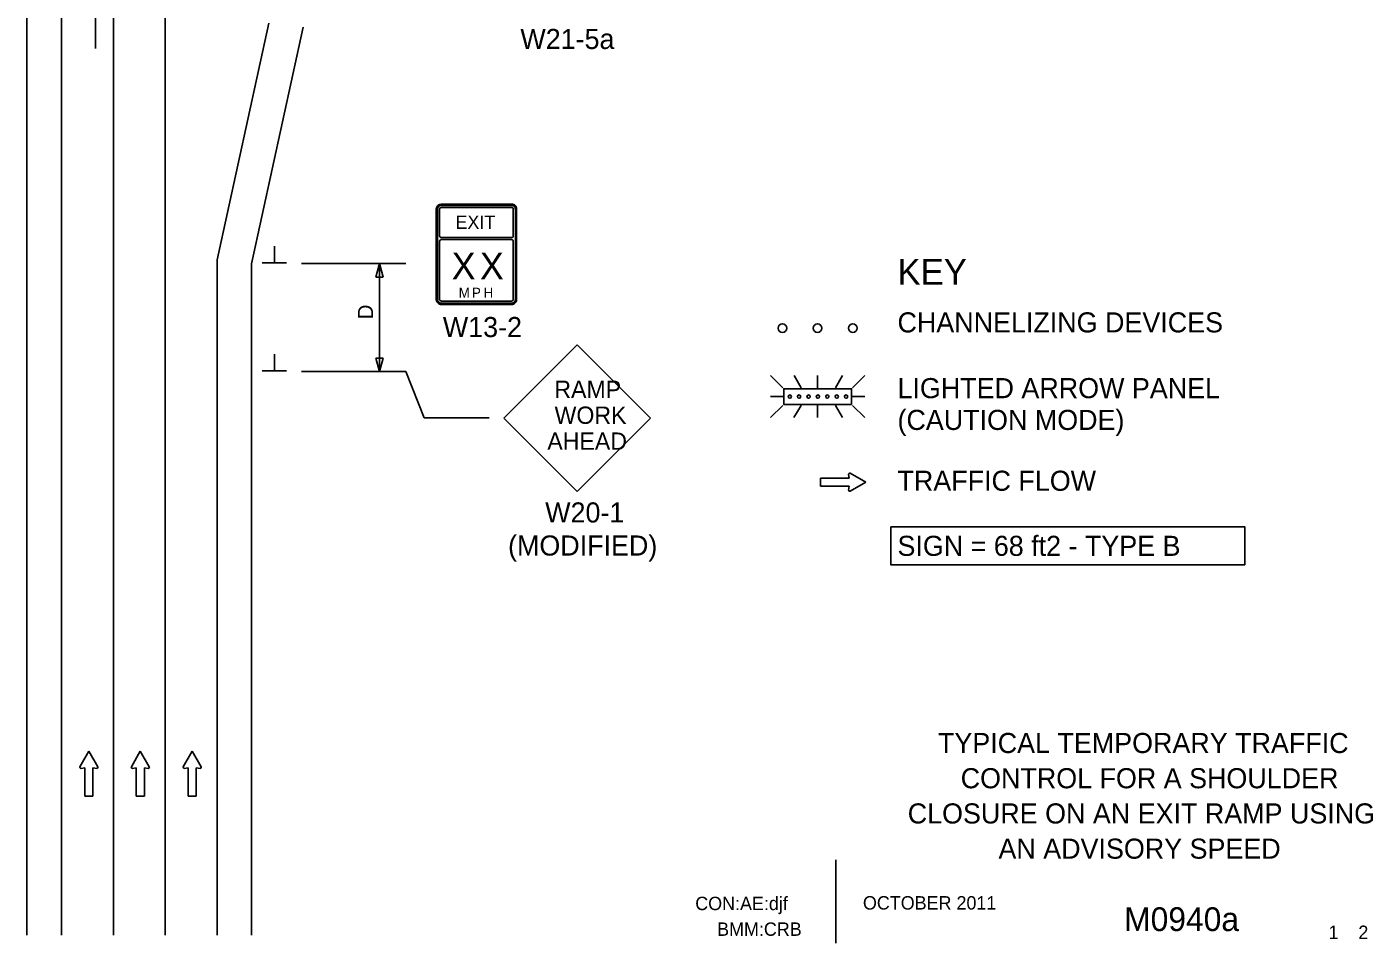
# Model space of a CAD drawing. Extents: x 16739 to 18471, y 6430 to 8295.
# Drawn here: x 16781 to 17404, y 7229 to 7653 of the extents above; entities that cross this region are included whole.
import ezdxf

# ---------------------------------------------------------------- set-up
doc = ezdxf.new("R2010")
doc.units = 0
for name, color, linetype in [('ALI_LEGAL_EX', 7, 'Continuous'), ('BORDER', 7, 'Continuous'), ('BORDER_SIGNAL_WO', 7, 'Continuous'), ('MT_SCRATCH_LEVEL_E', 7, 'Continuous'), ('PAVT_EDGE_EX', 7, 'Continuous'), ('TRAFFIC_SIGNS_PR', 7, 'Continuous'), ('TYPICAL_TEXT_DIMEN_EX', 7, 'Continuous'), ('TYPICAL_TEXT_DIMEN_PR', 7, 'Continuous')]:
    doc.layers.add(name, color=color, linetype=linetype)

msp = doc.modelspace()

# ---------------------------------------------------------------- linework, layer by layer
at = {"layer": 'ALI_LEGAL_EX'}
for p, q in [((16813.1, 7643.13), (16813.1, 8295.46)), ((16821.4, 8187.24), (16821.4, 7232.8)), ((16845.4, 8187.24), (16845.4, 7232.8))]:
    msp.add_line(p, q, dxfattribs=at)
for points in [[(16821.4, 7587.24), (16821.4, 7562.24)], [(16845.4, 7587.24), (16845.4, 7562.24)], [(16821.4, 7487.24), (16821.4, 7462.24)], [(16845.4, 7487.24), (16845.4, 7462.24)], [(16821.4, 7387.24), (16821.4, 7362.24)], [(16845.4, 7387.24), (16845.4, 7362.24)], [(16821.4, 7287.24), (16821.4, 7262.24)], [(16845.4, 7287.24), (16845.4, 7262.24)]]:
    msp.add_lwpolyline(points, dxfattribs=at)
at = {"layer": 'BORDER'}
msp.add_line((17155.75, 7229.07), (17155.75, 7267.6), dxfattribs=at)
at = {"layer": 'MT_SCRATCH_LEVEL_E'}
for p, q in [((17161.67, 7446.02), (17161.99, 7444.24)), ((17161.67, 7446.02), (17161.99, 7444.24)), ((17169.6, 7442.39), (17162.36, 7446.5)), ((17169.6, 7442.39), (17162.36, 7446.5)), ((17161.99, 7444.24), (17148.73, 7444.24)), ((17148.73, 7444.24), (17148.73, 7440.5)), ((17161.99, 7444.24), (17148.73, 7444.24)), ((17148.73, 7444.24), (17148.73, 7440.5)), ((17148.73, 7440.5), (17161.99, 7440.5)), ((17148.73, 7440.5), (17161.99, 7440.5)), ((17161.99, 7440.5), (17161.67, 7438.72)), ((17161.99, 7440.5), (17161.67, 7438.72)), ((17162.36, 7438.24), (17169.6, 7442.39)), ((17162.36, 7438.24), (17169.6, 7442.39)), ((16810.06, 7317.86), (16805.96, 7310.61)), ((16810.06, 7317.86), (16805.96, 7310.61)), ((16814.21, 7310.61), (16810.06, 7317.86)), ((16814.21, 7310.61), (16810.06, 7317.86)), ((16833.87, 7317.86), (16829.76, 7310.61)), ((16833.87, 7317.86), (16829.76, 7310.61)), ((16838.01, 7310.61), (16833.87, 7317.86)), ((16838.01, 7310.61), (16833.87, 7317.86)), ((16857.87, 7317.86), (16853.76, 7310.61)), ((16857.87, 7317.86), (16853.76, 7310.61)), ((16862.02, 7310.61), (16857.87, 7317.86)), ((16862.02, 7310.61), (16857.87, 7317.86)), ((16806.44, 7309.93), (16808.21, 7310.25)), ((16806.44, 7309.93), (16808.21, 7310.25)), ((16808.21, 7310.25), (16808.21, 7296.99)), ((16808.21, 7310.25), (16808.21, 7296.99)), ((16811.96, 7296.99), (16811.96, 7310.25)), ((16811.96, 7310.25), (16813.73, 7309.93)), ((16811.96, 7296.99), (16811.96, 7310.25)), ((16811.96, 7310.25), (16813.73, 7309.93)), ((16830.24, 7309.93), (16832.01, 7310.25)), ((16830.24, 7309.93), (16832.01, 7310.25)), ((16832.01, 7310.25), (16832.01, 7296.99)), ((16832.01, 7310.25), (16832.01, 7296.99)), ((16835.76, 7296.99), (16835.76, 7310.25)), ((16835.76, 7310.25), (16837.53, 7309.93)), ((16835.76, 7296.99), (16835.76, 7310.25)), ((16835.76, 7310.25), (16837.53, 7309.93)), ((16854.24, 7309.93), (16856.02, 7310.25)), ((16854.24, 7309.93), (16856.02, 7310.25)), ((16856.02, 7310.25), (16856.02, 7296.99)), ((16856.02, 7310.25), (16856.02, 7296.99)), ((16859.76, 7296.99), (16859.76, 7310.25)), ((16859.76, 7310.25), (16861.54, 7309.93)), ((16859.76, 7296.99), (16859.76, 7310.25)), ((16859.76, 7310.25), (16861.54, 7309.93)), ((16808.21, 7296.99), (16811.96, 7296.99)), ((16808.21, 7296.99), (16811.96, 7296.99)), ((16832.01, 7296.99), (16835.76, 7296.99)), ((16832.01, 7296.99), (16835.76, 7296.99)), ((16856.02, 7296.99), (16859.76, 7296.99)), ((16856.02, 7296.99), (16859.76, 7296.99))]:
    msp.add_line(p, q, dxfattribs=at)
for centre, start, end in [((17162.13, 7446.09), 60.42484, 189.96381), ((17162.13, 7446.09), 60.42484, 189.96381), ((17162.14, 7438.65), 170.03619, 299.77312), ((17162.14, 7438.65), 170.03619, 299.77312), ((16806.36, 7310.39), 150.42484, 279.96381), ((16806.36, 7310.39), 150.42484, 279.96381), ((16813.8, 7310.39), 260.03619, 29.77312), ((16813.8, 7310.39), 260.03619, 29.77312), ((16830.16, 7310.39), 150.42484, 279.96381), ((16830.16, 7310.39), 150.42484, 279.96381), ((16837.6, 7310.39), 260.03619, 29.77312), ((16837.6, 7310.39), 260.03619, 29.77312), ((16854.17, 7310.39), 150.42484, 279.96381), ((16854.17, 7310.39), 150.42484, 279.96381), ((16861.61, 7310.39), 260.03619, 29.77312), ((16861.61, 7310.39), 260.03619, 29.77312)]:
    msp.add_arc(centre, 0.463, start, end, dxfattribs=at)
at = {"layer": 'PAVT_EDGE_EX'}
for p, q in [((16781.4, 7232.8), (16781.4, 8077.7)), ((16797.4, 7232.8), (16797.4, 8077.7)), ((16893.33, 7654.82), (16869.4, 7545.32)), ((16909.24, 7653), (16885.31, 7543.5)), ((16869.4, 7232.8), (16869.4, 7545.32)), ((16885.31, 7232.8), (16885.31, 7543.7))]:
    msp.add_line(p, q, dxfattribs=at)
at = {"layer": 'TRAFFIC_SIGNS_PR'}
for p, q in [((17005.7, 7571.1), (16973.18, 7571.1)), ((16970.86, 7568.78), (16970.86, 7526.97)), ((17008.02, 7526.97), (17008.02, 7568.78)), ((16973.18, 7524.65), (17005.7, 7524.65)), ((17036.04, 7505.91), (17002.1, 7471.97)), ((17069.98, 7471.97), (17036.04, 7505.91)), ((17125.52, 7491.7), (17131.16, 7486.06)), ((17139.69, 7486.06), (17136.44, 7491.7)), ((17147.33, 7486.06), (17147.33, 7491.7)), ((17155.6, 7486.06), (17158.85, 7491.7)), ((17163.5, 7486.06), (17169.14, 7491.71)), ((17131.16, 7482), (17125.52, 7482)), ((17125.52, 7472.3), (17131.16, 7477.94)), ((17134.43, 7482), (17134.43, 7482)), ((17136.39, 7472.3), (17139.64, 7477.94)), ((17138.78, 7482), (17138.78, 7482)), ((17143.13, 7482), (17143.13, 7482)), ((17147.33, 7477.94), (17147.33, 7472.3)), ((17147.48, 7482), (17147.48, 7482)), ((17151.82, 7482), (17151.82, 7482)), ((17158.9, 7472.3), (17155.65, 7477.94)), ((17156.17, 7482), (17156.17, 7482)), ((17160.51, 7482), (17160.51, 7482)), ((17163.5, 7482), (17169.14, 7482)), ((17163.5, 7477.94), (17169.14, 7472.29)), ((17002.1, 7471.97), (17036.04, 7438.03)), ((17036.04, 7438.03), (17069.98, 7471.97))]:
    msp.add_line(p, q, dxfattribs=at)
for points in [[(17005.7, 7571.1), (16973.18, 7571.1)], [(16973.18, 7570.52), (17005.7, 7570.52)], [(17005.7, 7569.55), (16973.18, 7569.55)], [(16970.86, 7568.78), (16970.86, 7526.97)], [(16971.44, 7526.97), (16971.44, 7568.78)], [(16972.41, 7568.78), (16972.41, 7556.39)], [(17006.47, 7556.39), (17006.47, 7568.78)], [(17007.44, 7568.78), (17007.44, 7526.97)], [(17008.02, 7526.97), (17008.02, 7568.78)], [(16972.41, 7553.88), (16972.41, 7526.97)], [(16973.18, 7555.62), (17005.7, 7555.62)], [(17005.7, 7554.65), (16973.18, 7554.65)], [(17006.47, 7526.97), (17006.47, 7553.88)], [(16973.18, 7526.2), (17005.7, 7526.2)], [(17005.7, 7525.23), (16973.18, 7525.23)], [(16973.18, 7524.65), (17005.7, 7524.65)]]:
    msp.add_lwpolyline(points, dxfattribs=at)
msp.add_lwpolyline([(17163.03, 7478.4), (17131.62, 7478.4), (17131.62, 7485.6), (17163.03, 7485.6)], close=True, dxfattribs=at)
for centre, radius in [((17131.02, 7513.7), 2), ((17147.32, 7513.7), 2), ((17163.62, 7513.7), 2), ((17134.47, 7482), 0.758), ((17138.78, 7482), 0.758), ((17143.13, 7482), 0.758), ((17147.47, 7482), 0.758), ((17151.82, 7482), 0.758), ((17156.17, 7482), 0.758), ((17160.52, 7482), 0.758)]:
    msp.add_circle(centre, radius, dxfattribs=at)
for centre, radius, start, end in [((16973.18, 7568.78), 2.32, 90.00021, 179.99985), ((16973.18, 7568.78), 2.32, 90.00021, 179.99985), ((16973.18, 7568.78), 1.74, 90.00021, 179.99985), ((16973.18, 7568.78), 0.774, 90.00021, 179.99985), ((17005.7, 7568.78), 2.32, 0, 90.00021), ((17005.7, 7568.78), 2.32, 0, 90.00021), ((17005.7, 7568.78), 1.74, 360, 90.00021), ((17005.7, 7568.78), 0.774, 0, 90.00021), ((16973.18, 7556.39), 0.774, 179.99985, 270.00006), ((16973.18, 7553.88), 0.774, 90.00021, 179.99985), ((17005.7, 7556.39), 0.774, 270.00006, 0.00027), ((17005.7, 7553.88), 0.774, 0, 90.00021), ((16973.18, 7526.97), 2.32, 179.99985, 270.00006), ((16973.18, 7526.97), 2.32, 179.99985, 270.00006), ((16973.18, 7526.97), 1.74, 179.99985, 270.00006), ((16973.18, 7526.97), 0.774, 179.99985, 270.00006), ((17005.7, 7526.97), 2.32, 270.00006, 0.00027), ((17005.7, 7526.97), 2.32, 270.00006, 0.00027), ((17005.7, 7526.97), 1.74, 270.00006, 0.00027), ((17005.7, 7526.97), 0.774, 270.00006, 0.00027)]:
    msp.add_arc(centre, radius, start, end, dxfattribs=at)
at = {"layer": 'TYPICAL_TEXT_DIMEN_PR'}
for p, q in [((16895.94, 7543.86), (16895.94, 7551.65)), ((16895.94, 7543.86), (16890.32, 7543.86)), ((16901.57, 7543.86), (16895.94, 7543.86)), ((16908.53, 7543.57), (16956.8, 7543.57)), ((16944.51, 7543.57), (16942.84, 7537.32)), ((16944.51, 7493.57), (16944.51, 7543.57)), ((16946.19, 7537.32), (16944.51, 7543.57)), ((16942.84, 7537.32), (16944.51, 7537.32)), ((16944.51, 7537.32), (16946.19, 7537.32)), ((16895.94, 7493.86), (16895.94, 7501.65)), ((16944.51, 7493.57), (16942.84, 7499.82)), ((16942.84, 7499.82), (16944.51, 7499.82)), ((16944.51, 7499.82), (16946.19, 7499.82)), ((16946.19, 7499.82), (16944.51, 7493.57)), ((16895.94, 7493.86), (16890.32, 7493.86)), ((16901.57, 7493.86), (16895.94, 7493.86)), ((16908.53, 7493.57), (16956.8, 7493.57)), ((16965.2, 7472.22), (16956.8, 7493.57)), ((16965.2, 7472.22), (16995.25, 7472.22))]:
    msp.add_line(p, q, dxfattribs=at)
msp.add_lwpolyline([(17181.16, 7421.74), (17345.03, 7421.74), (17345.03, 7404.16), (17181.16, 7404.16)], close=True, dxfattribs=at)

# ---------------------------------------------------------------- texts
at = {"layer": 'BORDER_SIGNAL_WO'}
for s, height, p in [('TYPICAL TEMPORARY TRAFFIC', 9.3, (17203.04, 7317.02)), ('CONTROL FOR A SHOULDER', 9.3, (17213.54, 7300.72)), ('CLOSURE ON AN EXIT RAMP USING', 9.3, (17189.03, 7284.42)), ('AN ADVISORY SPEED', 9.3, (17231.02, 7268.12)), ('CON:AE:djf  ', 6.2, (17090.69, 7244.31)), ('    OCTOBER 2011    ', 6.2, (17159.08, 7244.59)), ('    M0940a   ', 11, (17272.86, 7234.63)), ('BMM:CRB   ', 6.2, (17100.81, 7232.42)), (' 1    2 ', 6.2, (17381.45, 7230.95))]:
    msp.add_text(s, height=height, dxfattribs=at).set_placement(p)
at = {"layer": 'TRAFFIC_SIGNS_PR'}
for s, height, p in [('W21-5a', 9.3, (17009.76, 7642.88)), ('EXIT', 6.194, (16979.73, 7559.62)), ('X', 12.39, (16977.98, 7536.26)), ('X', 12.39, (16991.04, 7536.26)), ('M', 4.65, (16981.22, 7527.75)), ('P', 4.65, (16987.34, 7527.75)), ('H', 4.65, (16992.69, 7527.75)), ('W13-2', 9.3, (16973.88, 7509.55)), ('RAMP', 8, (17025.49, 7481.39)), ('WORK', 8, (17025.6, 7469.39)), ('AHEAD', 8, (17022.24, 7457.39)), ('W20-1', 9.3, (17021.25, 7423.73)), ('(MODIFIED)', 9.3, (17004.06, 7408.43))]:
    msp.add_text(s, height=height, dxfattribs=at).set_placement(p)
at = {"layer": 'TYPICAL_TEXT_DIMEN_EX'}
for s, height, p in [('KEY', 12, (17184.3, 7533.75)), ('CHANNELIZING DEVICES', 9.3, (17184.3, 7511.7)), ('LIGHTED ARROW PANEL', 9.3, (17184.3, 7481.27)), ('(CAUTION MODE)', 9.3, (17184.3, 7466.57)), ('TRAFFIC FLOW', 9.3, (17184.3, 7438.4))]:
    msp.add_text(s, height=height, dxfattribs=at).set_placement(p)
at = {"layer": 'TYPICAL_TEXT_DIMEN_PR'}
msp.add_text('D', height=7, rotation=89.84604, dxfattribs=at).set_placement((16941.57, 7517.81))
msp.add_text('SIGN = 68 ft2 - TYPE B', height=9.3, dxfattribs=at).set_placement((17184.3, 7408.28))

doc.saveas('drawing.dxf')
